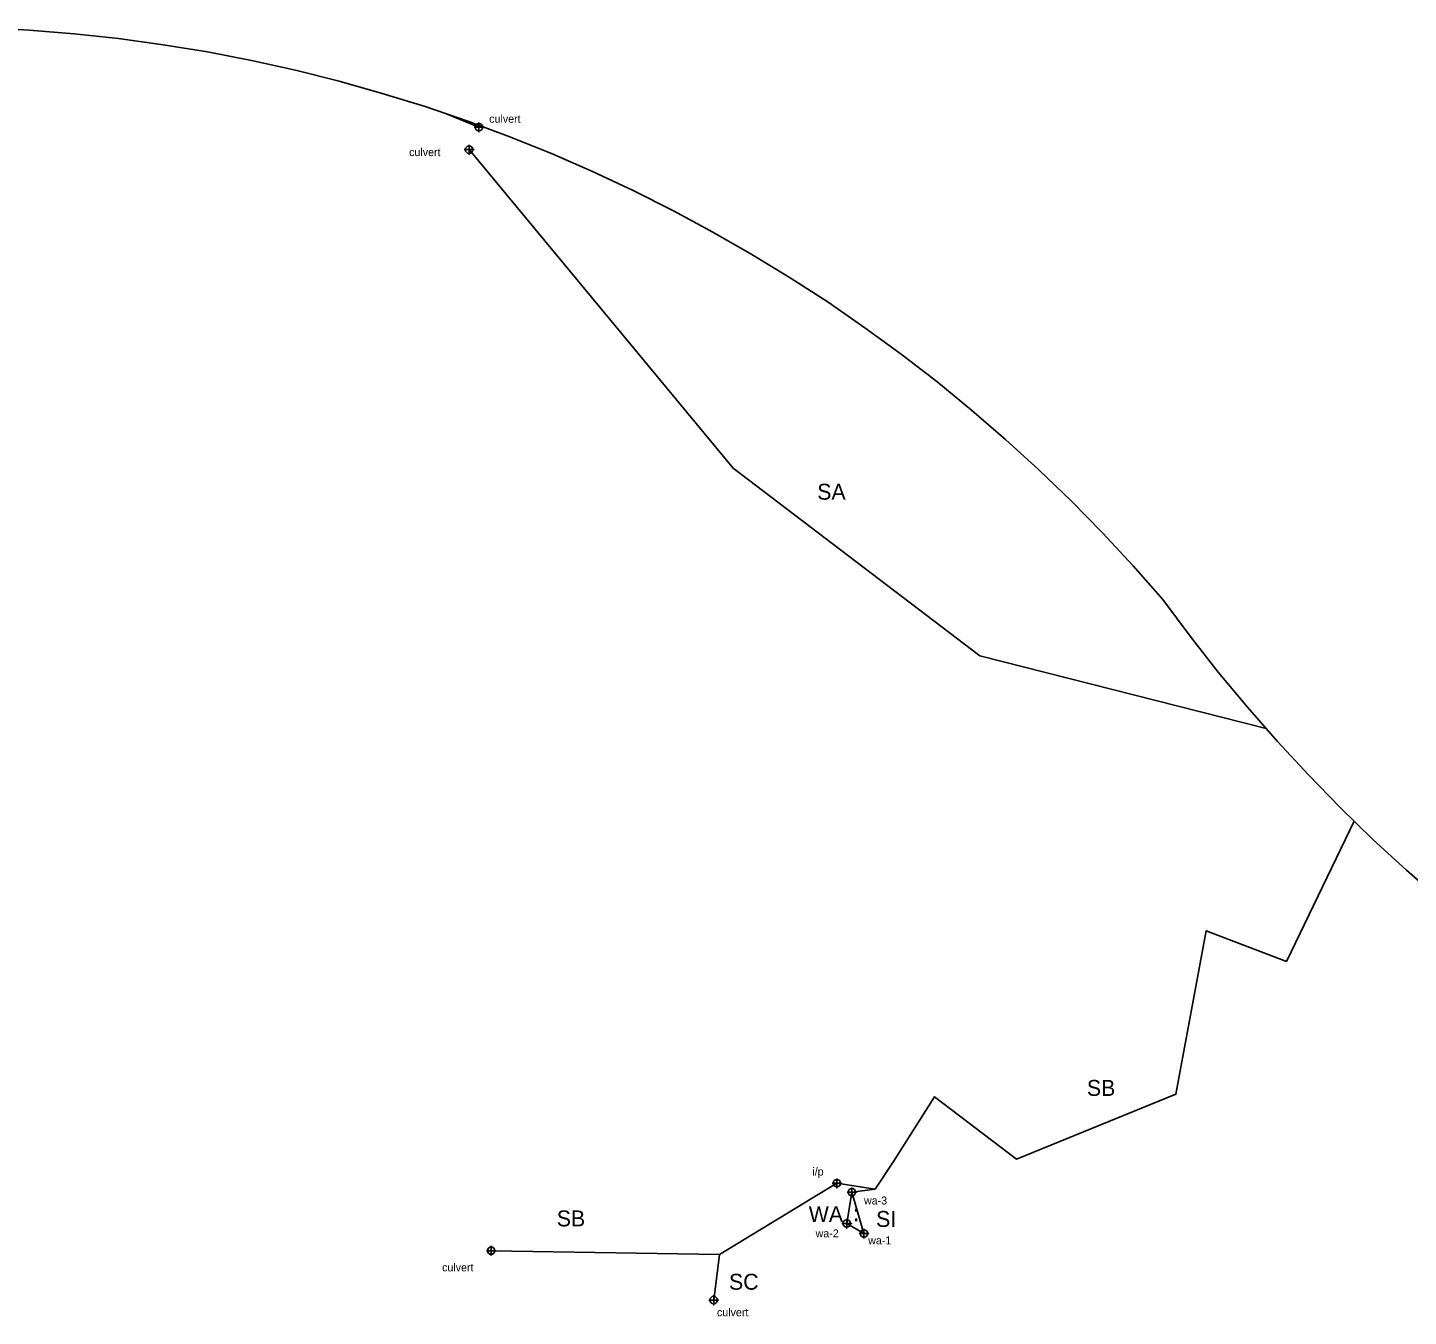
# Model space of a CAD drawing. Extents: x 1637473 to 1644249, y 841388 to 844031.
# Drawn here: x 1641726 to 1642592, y 842450 to 843257 of the extents above; entities that cross this region are included whole.
import ezdxf

# ---------------------------------------------------------------- set-up
doc = ezdxf.new("R2010")
doc.units = 0
for name, color, linetype in [('Default', 7, 'Continuous'), ('Exist Environmental Wetland Boundary', 7, 'Continuous'), ('Exist Environmental Wetland Boundary Cogo Number', 7, 'Continuous'), ('Exist Environmental Wetland Boundary Cogo Point CELL', 7, 'Continuous'), ('Exist Environmental Wetland Boundary Text', 7, 'Continuous'), ('Exist Hydro Jurisdictional Stream or Body of Water Mitigable', 7, 'Continuous'), ('Exist Hydro Jurisdictional Stream or Body of Water Mitigable Cogo Number', 7, 'Continuous'), ('Exist Hydro Jurisdictional Stream or Body of Water Mitigable Cogo Point CELL', 7, 'Continuous'), ('Exist Hydro Jurisdictional Stream or Body of Water Mitigable Text', 7, 'Continuous')]:
    doc.layers.add(name, color=color, linetype=linetype)

msp = doc.modelspace()

# ---------------------------------------------------------------- linework, layer by layer
at = {"layer": 'Default'}
msp.add_lwpolyline([(1641699.28, 843257.48), (1641727.39, 843255.96), (1641755.46, 843253.67), (1641783.45, 843250.61), (1641811.35, 843246.79), (1641839.13, 843242.2), (1641866.77, 843236.85), (1641894.26, 843230.74), (1641921.57, 843223.88), (1641948.68, 843216.27), (1641975.57, 843207.93), (1642002.23, 843198.84), (1642028.62, 843189.03), (1642054.73, 843178.5), (1642080.55, 843167.26), (1642106.05, 843155.31), (1642131.21, 843142.67), (1642156.01, 843129.34), (1642180.44, 843115.34), (1642204.47, 843100.67), (1642228.1, 843085.35), (1642251.29, 843069.38), (1642274.04, 843052.78), (1642296.32, 843035.57), (1642318.12, 843017.75), (1642339.43, 842999.34), (1642360.22, 842980.35), (1642380.48, 842960.8), (1642400.2, 842940.7), (1642419.36, 842920.07), (1642437.95, 842898.91), (1642455.02, 842875.98), (1642472.69, 842853.51), (1642490.96, 842831.52), (1642509.8, 842810.02), (1642529.21, 842789.04), (1642549.18, 842768.58), (1642569.68, 842748.65), (1642590.7, 842729.29), (1642612.24, 842710.48)], dxfattribs=at)
at = {"layer": 'Exist Environmental Wetland Boundary'}
msp.add_lwpolyline([(1642243.07, 842527.48), (1642250.63, 842501.55), (1642239.86, 842507.83)], close=True, dxfattribs=at)
at = {"layer": 'Exist Environmental Wetland Boundary Cogo Point CELL'}
for points in [[(1642243.07, 842530.48), (1642243.07, 842524.48), (1642243.07, 842527.48), (1642246.07, 842527.48), (1642240.07, 842527.48)], [(1642239.86, 842510.83), (1642239.86, 842504.83), (1642239.86, 842507.83), (1642242.86, 842507.83), (1642236.86, 842507.83)], [(1642250.63, 842504.55), (1642250.63, 842498.55), (1642250.63, 842501.55), (1642253.63, 842501.55), (1642247.63, 842501.55)]]:
    msp.add_lwpolyline(points, dxfattribs=at)
for centre in [(1642243.07, 842527.48), (1642239.86, 842507.83), (1642250.63, 842501.55)]:
    msp.add_circle(centre, 2.34, dxfattribs=at)
at = {"layer": 'Exist Hydro Jurisdictional Stream or Body of Water Mitigable'}
for p, q in [((1641989.45, 843203.2), (1642009.28, 843195.09)), ((1642156.43, 842459.85), (1642160.11, 842488.32))]:
    msp.add_line(p, q, dxfattribs=at)
for points in [[(1642003.09, 843180.98), (1642168.56, 842981.28), (1642323.23, 842863.72), (1642502.74, 842818.08)], [(1642233.66, 842533.09), (1642257.57, 842529.26), (1642269.17, 842546.62), (1642294.93, 842587.34), (1642346.31, 842548.24), (1642446.14, 842588.91), (1642465.23, 842691.37), (1642515.44, 842672.17), (1642558.03, 842759.97)], [(1642016.94, 842490.81), (1642160.11, 842488.32), (1642233.66, 842533.09)], [(1642250.63, 842501.55), (1642243.07, 842527.48), (1642257.57, 842529.26)], [(1642245.04, 842515.88), (1642245.69, 842515.88), (1642245.69, 842517.06), (1642245.69, 842515.88), (1642246.33, 842515.88)], [(1642245.04, 842509.69), (1642245.69, 842509.69), (1642245.69, 842510.88), (1642245.69, 842509.69), (1642246.33, 842509.69)], [(1642245.69, 842504.43), (1642245.69, 842504.69), (1642245.69, 842504.43)]]:
    msp.add_lwpolyline(points, dxfattribs=at)
for centre, radius, start, end in [((1642244.77, 842515.81), 0.922, 4.14034, 67.53497), ((1642247.06, 842515.42), 1.44, 124.45315, 161.62219), ((1642244.77, 842509.63), 0.922, 4.14034, 67.53497), ((1642247.06, 842509.24), 1.44, 122.12745, 161.62219), ((1642247.06, 842503.05), 1.44, 122.12745, 129.48808)]:
    msp.add_arc(centre, radius, start, end, dxfattribs=at)
at = {"layer": 'Exist Hydro Jurisdictional Stream or Body of Water Mitigable Cogo Point CELL'}
for points in [[(1642009.28, 843198.09), (1642009.28, 843192.09), (1642009.28, 843195.09), (1642012.28, 843195.09), (1642006.28, 843195.09)], [(1642003.09, 843183.98), (1642003.09, 843177.98), (1642003.09, 843180.98), (1642006.09, 843180.98), (1642000.09, 843180.98)], [(1642233.66, 842536.09), (1642233.66, 842530.09), (1642233.66, 842533.09), (1642236.66, 842533.09), (1642230.66, 842533.09)], [(1642016.94, 842493.81), (1642016.94, 842487.81), (1642016.94, 842490.81), (1642019.94, 842490.81), (1642013.94, 842490.81)], [(1642156.43, 842462.85), (1642156.43, 842456.85), (1642156.43, 842459.85), (1642159.43, 842459.85), (1642153.43, 842459.85)]]:
    msp.add_lwpolyline(points, dxfattribs=at)
for centre in [(1642009.28, 843195.09), (1642003.09, 843180.98), (1642233.66, 842533.09), (1642016.94, 842490.81), (1642156.43, 842459.85)]:
    msp.add_circle(centre, 2.34, dxfattribs=at)

# ---------------------------------------------------------------- texts
at = {"layer": 'Exist Environmental Wetland Boundary Cogo Number'}
for s, p in [('wa-3', (1642250.66, 842519.76)), ('wa-2', (1642220.33, 842499.15)), ('wa-1', (1642253.32, 842494.75))]:
    msp.add_text(s, height=5, dxfattribs=at).set_placement(p)
at = {"layer": 'Exist Environmental Wetland Boundary Text'}
msp.add_text('WA', height=10, dxfattribs=at).set_placement((1642216.02, 842508.7))
at = {"layer": 'Exist Hydro Jurisdictional Stream or Body of Water Mitigable Cogo Number'}
for s, p in [('culvert', (1642015.73, 843197.84)), ('culvert', (1641965.52, 843176.93)), ('i/p', (1642218.32, 842537.9)), ('culvert', (1641986.18, 842477.84)), ('culvert', (1642158.49, 842449.69))]:
    msp.add_text(s, height=5, dxfattribs=at).set_placement(p)
at = {"layer": 'Exist Hydro Jurisdictional Stream or Body of Water Mitigable Text'}
for s, p in [('SA', (1642221.34, 842961.56)), ('SB', (1642390.37, 842587.83)), ('SB', (1642058.06, 842506.04)), ('SI', (1642258.25, 842505.68)), ('SC', (1642166.02, 842466.32))]:
    msp.add_text(s, height=10, dxfattribs=at).set_placement(p)

doc.saveas('drawing.dxf')
